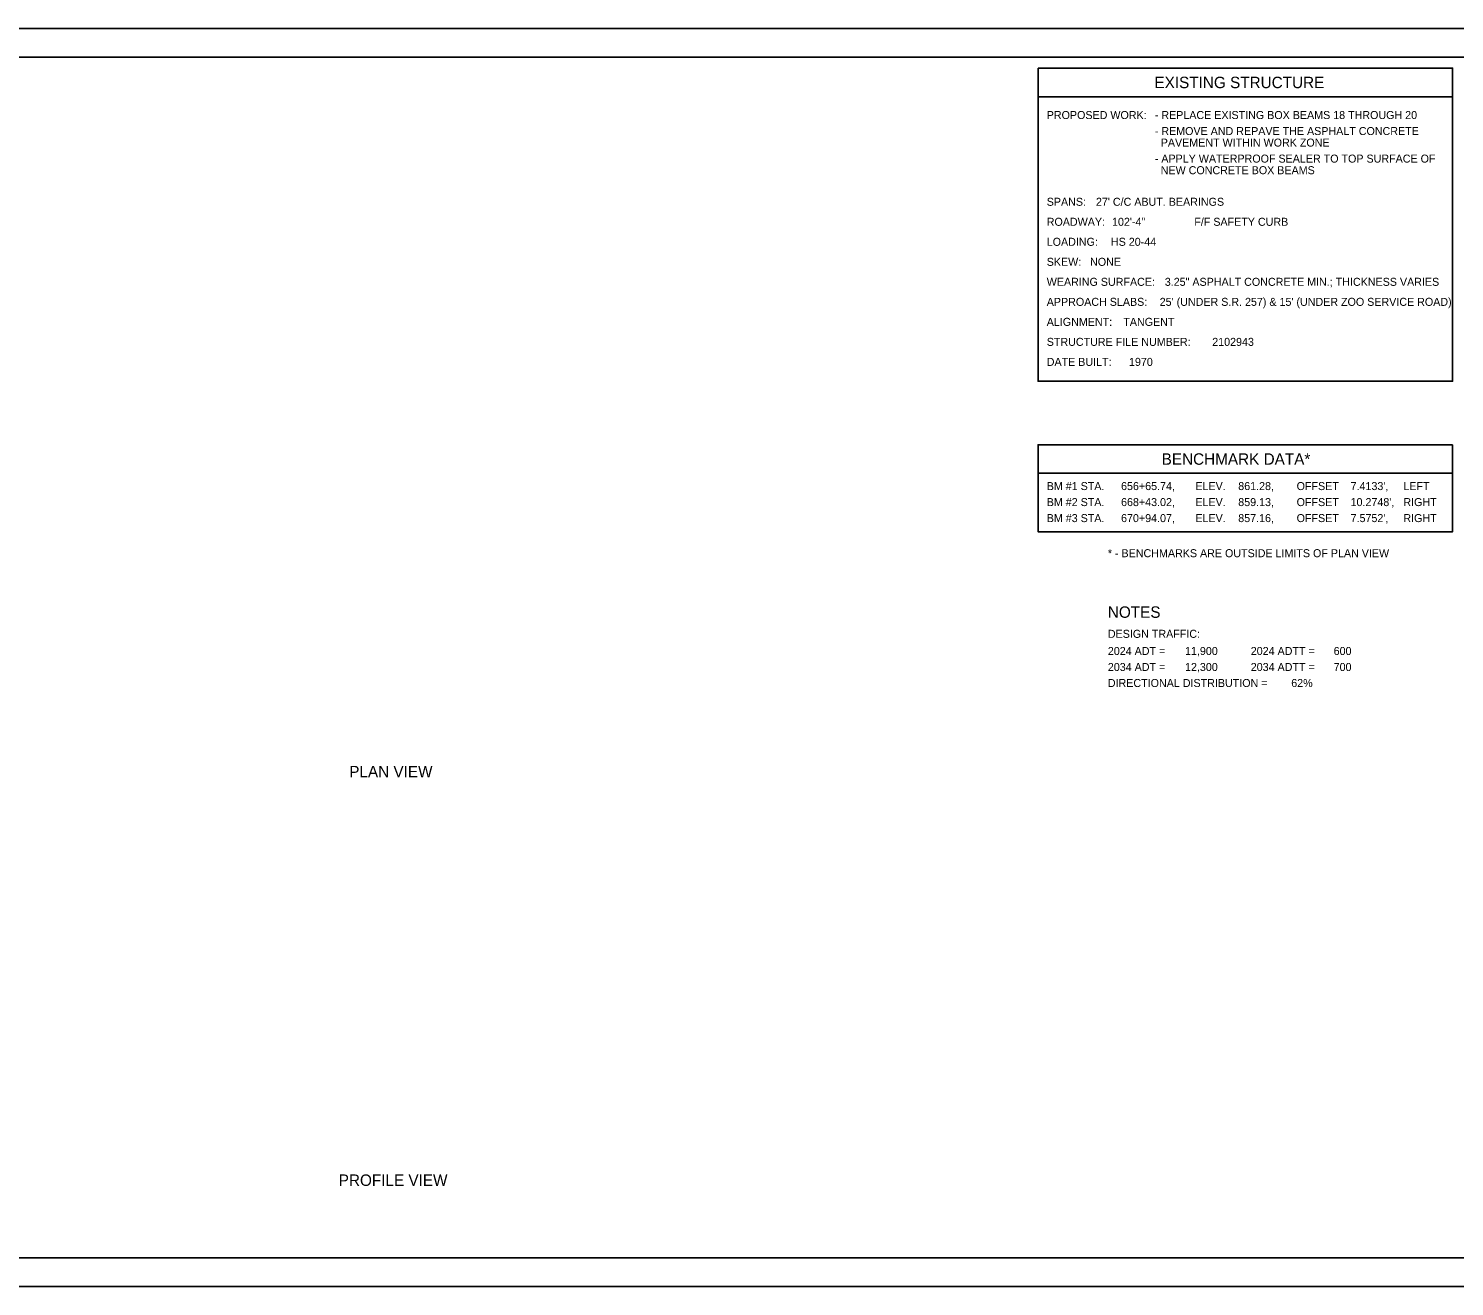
# Model space of a CAD drawing. Extents: x -8 to 51.8, y 0 to 37.2.
# Drawn here: x 6.85 to 31.8, y 0 to 22 of the extents above; entities that cross this region are included whole.
import ezdxf

# ---------------------------------------------------------------- set-up
doc = ezdxf.new("R2010")
doc.units = 0
for name, color, linetype in [('SH_Border', 7, 'Continuous'), ('SH_Cut_Line', 7, 'Continuous'), ('SH_Data', 7, 'Continuous')]:
    doc.layers.add(name, color=color, linetype=linetype)

msp = doc.modelspace()

# ---------------------------------------------------------------- linework, layer by layer
at = {"layer": 'SH_Border'}
msp.add_lwpolyline([(1.5, 21.5), (33.5, 21.5), (33.5, 0.5), (1.5, 0.5)], close=True, dxfattribs=at)
at = {"layer": 'SH_Cut_Line'}
msp.add_lwpolyline([(0, 0), (34, 0), (34, 22), (0, 22)], close=True, dxfattribs=at)
at = {"layer": 'SH_Data'}
for p, q in [((31.763, 20.807), (24.513, 20.807)), ((24.513, 14.221), (31.763, 14.221))]:
    msp.add_line(p, q, dxfattribs=at)
for points in [[(24.513, 21.307), (31.763, 21.307), (31.763, 15.83), (24.513, 15.83)], [(31.763, 14.721), (24.513, 14.721), (24.513, 13.198), (31.763, 13.198)]]:
    msp.add_lwpolyline(points, close=True, dxfattribs=at)

# ---------------------------------------------------------------- texts
for s, height, p in [('EXISTING STRUCTURE', 0.2, (26.547, 20.957)), ('PROPOSED WORK:', 0.14, (24.663, 20.417)), ('- REPLACE EXISTING BOX BEAMS 18 THROUGH 20', 0.14, (26.553, 20.417)), ('- REMOVE AND REPAVE THE ASPHALT CONCRETE', 0.14, (26.553, 20.137)), ('  PAVEMENT WITHIN WORK ZONE', 0.14, (26.553, 19.935)), ('- APPLY WATERPROOF SEALER TO TOP SURFACE OF', 0.14, (26.553, 19.655)), ('  NEW CONCRETE BOX BEAMS', 0.14, (26.553, 19.452)), ('SPANS:', 0.14, (24.663, 18.9)), ("27' C/C ABUT. BEARINGS", 0.14, (25.524, 18.9)), ('ROADWAY:', 0.14, (24.663, 18.55)), ('102\'-4"', 0.14, (25.805, 18.55)), ('F/F SAFETY CURB', 0.14, (27.244, 18.55)), ('LOADING:', 0.14, (24.663, 18.2)), ('HS 20-44', 0.14, (25.786, 18.2)), ('SKEW:', 0.14, (24.663, 17.85)), ('NONE', 0.14, (25.421, 17.85)), ('WEARING SURFACE:', 0.14, (24.663, 17.5)), ('3.25" ASPHALT CONCRETE MIN.; THICKNESS VARIES', 0.14, (26.728, 17.5)), ('APPROACH SLABS:', 0.14, (24.663, 17.15)), ("25' (UNDER S.R. 257) & 15' (UNDER ZOO SERVICE ROAD)", 0.14, (26.639, 17.15)), ('ALIGNMENT:', 0.14, (24.663, 16.8)), ('TANGENT', 0.14, (26.002, 16.8)), ('STRUCTURE FILE NUMBER:', 0.14, (24.663, 16.45)), ('2102943', 0.14, (27.558, 16.45)), ('DATE BUILT:', 0.14, (24.663, 16.1)), ('1970', 0.14, (26.102, 16.1)), ('BENCHMARK DATA*', 0.2, (26.673, 14.371)), ('BM #1 STA.', 0.14, (24.663, 13.928)), ('656+65.74,', 0.14, (25.963, 13.928)), ('ELEV.', 0.14, (27.263, 13.928)), ('861.28,', 0.14, (28.013, 13.928)), ('OFFSET', 0.14, (29.034, 13.928)), ("7.4133',", 0.14, (29.978, 13.928)), ('LEFT', 0.14, (30.901, 13.928)), ('BM #2 STA.', 0.14, (24.663, 13.648)), ('668+43.02,', 0.14, (25.963, 13.648)), ('ELEV.', 0.14, (27.263, 13.648)), ('859.13,', 0.14, (28.013, 13.648)), ('OFFSET', 0.14, (29.034, 13.648)), ("10.2748',", 0.14, (29.978, 13.648)), ('RIGHT', 0.14, (30.901, 13.648)), ('BM #3 STA.', 0.14, (24.663, 13.368)), ('670+94.07,', 0.14, (25.963, 13.368)), ('ELEV.', 0.14, (27.263, 13.368)), ('857.16,', 0.14, (28.013, 13.368)), ('OFFSET', 0.14, (29.034, 13.368)), ("7.5752',", 0.14, (29.978, 13.368)), ('RIGHT', 0.14, (30.901, 13.368)), ('* - BENCHMARKS ARE OUTSIDE LIMITS OF PLAN VIEW', 0.14, (25.732, 12.754)), ('NOTES', 0.2, (25.732, 11.694)), ('DESIGN TRAFFIC:', 0.14, (25.732, 11.344)), ('2024 ADT =', 0.14, (25.732, 11.044)), ('11,900', 0.14, (27.082, 11.044)), ('2024 ADTT =', 0.14, (28.232, 11.044)), ('600', 0.14, (29.682, 11.044)), ('2034 ADT =', 0.14, (25.732, 10.764)), ('12,300', 0.14, (27.082, 10.764)), ('2034 ADTT =', 0.14, (28.232, 10.764)), ('700', 0.14, (29.682, 10.764)), ('DIRECTIONAL DISTRIBUTION =', 0.14, (25.732, 10.484)), ('62%', 0.14, (28.94, 10.484)), ('PLAN VIEW', 0.2, (12.463, 8.904)), ('PROFILE VIEW', 0.2, (12.279, 1.759))]:
    msp.add_text(s, height=height, dxfattribs=at).set_placement(p)

doc.saveas('drawing.dxf')
